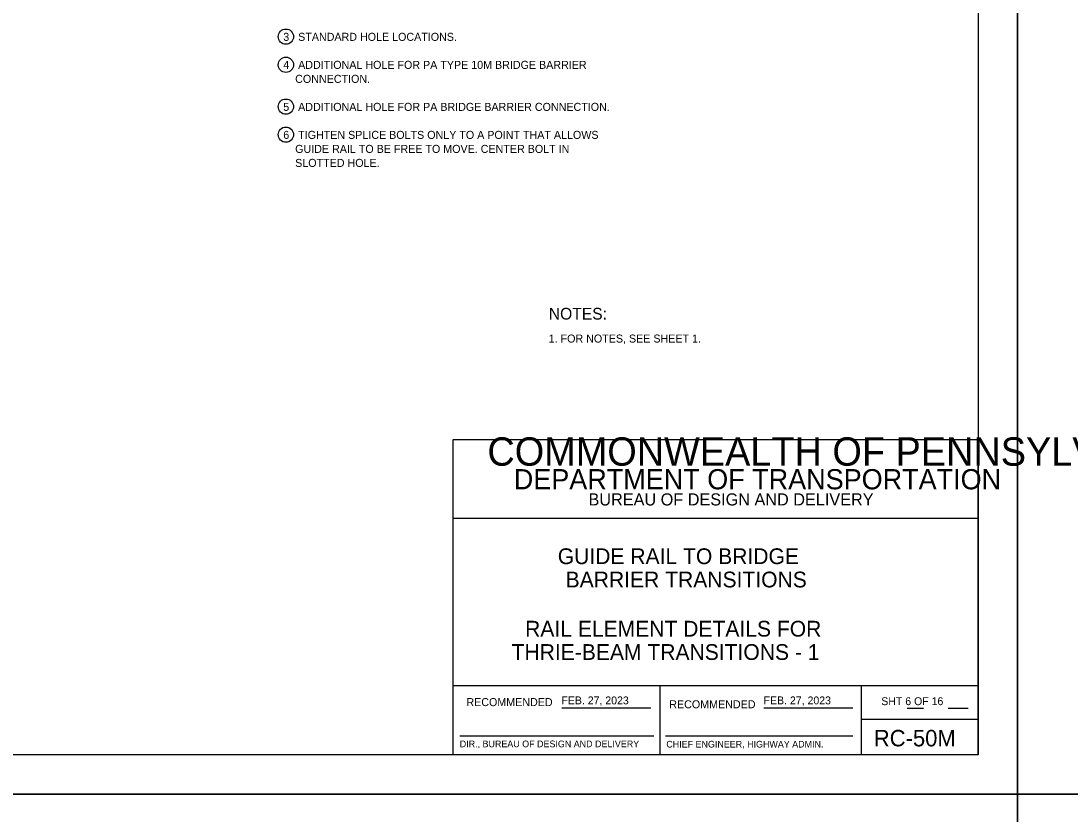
# Model space of a CAD drawing. Extents: x 632007860 to 635435983, y 295418622 to 297794622.
# Drawn here: x 633310414 to 633709860, y 296599122 to 296901105 of the extents above; entities that cross this region are included whole.
import ezdxf

# ---------------------------------------------------------------- set-up
doc = ezdxf.new("R2010")
doc.units = 0
for name, color, linetype in [('1', 7, 'Continuous'), ('2', 7, 'Continuous'), ('4', 7, 'Continuous'), ('PLT-BNDY', 7, 'Continuous'), ('S-DETL-DIMS', 7, 'Continuous'), ('S-DETL-T120', 7, 'Continuous'), ('S-DETL-T175', 7, 'Continuous')]:
    doc.layers.add(name, color=color, linetype=linetype)

msp = doc.modelspace()

# ---------------------------------------------------------------- linework, layer by layer
at = {"layer": '1'}
for p, q in [((633674860, 297185622), (633674860, 296621622)), ((633674860, 296741622), (633474860, 296741622)), ((633474860, 296741622), (633474860, 296621622)), ((633674860, 296711622), (633474860, 296711622)), ((633674860, 296647981), (633474860, 296647981)), ((633553661, 296647981), (633553661, 296621622)), ((633630362, 296647981), (633630362, 296621622)), ((633516325, 296639611), (633550211, 296639611)), ((633593323, 296639611), (633627193, 296639611)), ((633647906, 296639373), (633654048, 296639373)), ((633663427, 296639373), (633671073, 296639373)), ((633630362, 296635300), (633674860, 296635300)), ((633477485, 296628918), (633551385, 296628918)), ((633555791, 296628918), (633627131, 296628918)), ((633674860, 296621622), (632888860, 296621622))]:
    msp.add_line(p, q, dxfattribs=at)
at = {"layer": '4'}
msp.add_line((633674860, 296621622), (633674860, 296741622), dxfattribs=at)
at = {"layer": 'PLT-BNDY'}
for points in [[(632848860, 297200622), (633689860, 297200622), (633689860, 296606622), (632848860, 296606622)], [(633689860, 297200622), (634530860, 297200622), (634530860, 296606622), (633689860, 296606622)], [(632848860, 296606622), (633689860, 296606622), (633689860, 296012622), (632848860, 296012622)], [(633689860, 296606622), (634530860, 296606622), (634530860, 296012622), (633689860, 296012622)]]:
    msp.add_lwpolyline(points, close=True, dxfattribs=at)
at = {"layer": 'S-DETL-DIMS'}
for centre in [(633411296, 296895136), (633411296, 296884418), (633411296, 296868482), (633411296, 296857814)]:
    msp.add_circle(centre, 2906, dxfattribs=at)

# ---------------------------------------------------------------- texts
at = {"layer": '1'}
for s, height, p in [('COMMONWEALTH OF PENNSYLVANIA', 10783.37, (633488011, 296731766)), ('DEPARTMENT OF TRANSPORTATION', 7684.29, (633498072, 296722771)), ('BUREAU OF DESIGN AND DELIVERY', 4622.09, (633526520, 296716609)), ('RECOMMENDED', 3048, (633480023, 296640216)), ('FEB. 27, 2023', 3000, (633516186, 296640887)), ('RECOMMENDED', 3048, (633557267, 296639379)), ('FEB. 27, 2023', 3000, (633593184, 296640887)), ('SHT 6 OF 16', 3000, (633637991, 296640576)), ('APPROVED', 19.2, (633517883, 296639554)), ('RC-50M', 6267.5, (633635143, 296624881)), ('DIR., BUREAU OF DESIGN AND DELIVERY', 2540, (633477485, 296624554)), ('CHIEF ENGINEER, HIGHWAY ADMIN.', 2540, (633556144, 296624445))]:
    msp.add_text(s, height=height, dxfattribs=at).set_placement(p)
at = {"layer": '2'}
for s, p in [('GUIDE RAIL TO BRIDGE', (633514804, 296694287)), ('BARRIER TRANSITIONS', (633517804, 296685412)), ('RAIL ELEMENT DETAILS FOR', (633502376, 296666686)), ('THRIE-BEAM TRANSITIONS - 1', (633497226, 296657804))]:
    msp.add_text(s, height=6000, dxfattribs=at).set_placement(p)
at = {"layer": 'S-DETL-T120'}
for s, p in [('3   STANDARD HOLE LOCATIONS.', (633410287, 296893543)), ('4   ADDITIONAL HOLE FOR PA TYPE 10M BRIDGE BARRIER', (633410287, 296882875)), ('    CONNECTION.', (633410287, 296877541)), ('5   ADDITIONAL HOLE FOR PA BRIDGE BARRIER CONNECTION.', (633410287, 296866873)), ('6   TIGHTEN SPLICE BOLTS ONLY TO A POINT THAT ALLOWS', (633410287, 296856205)), ('    GUIDE RAIL TO BE FREE TO MOVE. CENTER BOLT IN', (633410287, 296850871)), ('    SLOTTED HOLE.', (633410287, 296845537))]:
    msp.add_text(s, height=3048.01, dxfattribs=at).set_placement(p)
msp.add_text('1. FOR NOTES, SEE SHEET 1.', height=3048.06, rotation=360, dxfattribs=at).set_placement((633511347, 296778648))
at = {"layer": 'S-DETL-T175'}
msp.add_text('NOTES:', height=4450, dxfattribs=at).set_placement((633511390, 296787412))

doc.saveas('drawing.dxf')
